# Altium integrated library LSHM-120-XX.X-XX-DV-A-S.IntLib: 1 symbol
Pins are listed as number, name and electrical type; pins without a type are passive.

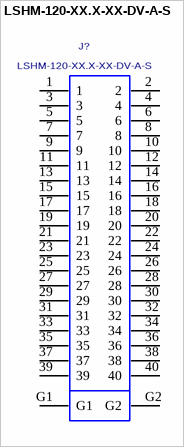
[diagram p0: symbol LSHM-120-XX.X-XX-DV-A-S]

## LSHM-120-XX.X-XX-DV-A-S
designator J?
0.50MM TERMINAL/SOCKET COMBO,40PINS.; MANUFACTURER: SAMTEC
footprint LSHM-120-XX.X-XX-DV-A-S
pins: 1, 2, 3, 4, 5, 6, 7, 8, 9, 10, 11, 12, 13, 14, 15, 16, 17, 18, 19, 20, 21, 22, 23, 24, 25, 26, 27, 28, 29, 30, 31, 32, 33, 34, 35, 36, 37, 38, 39, 40, G1, G2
